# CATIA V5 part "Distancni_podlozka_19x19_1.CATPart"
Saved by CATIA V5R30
Part number: Distancni_podlozka_19x19_1
Definition: EH 6281_19x19_2
Nomenclature: EH 6281_19x19_2
Source: Unknown
Description: PART--DESC
Bounding box of the stored display mesh (mm): x -139 to -120, y 9.01 to 27.99, z 20.7 to 39.7
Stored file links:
  E:\Bakalarka\Model\Forma_v7\Distancni_podlozka_19x19_1.CATPart
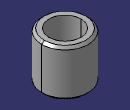
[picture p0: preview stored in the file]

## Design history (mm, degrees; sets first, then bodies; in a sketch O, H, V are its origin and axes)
Body1 "MANIFOLD_SOLID_BREP #3714" (main body)
  Solid1: solid without history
